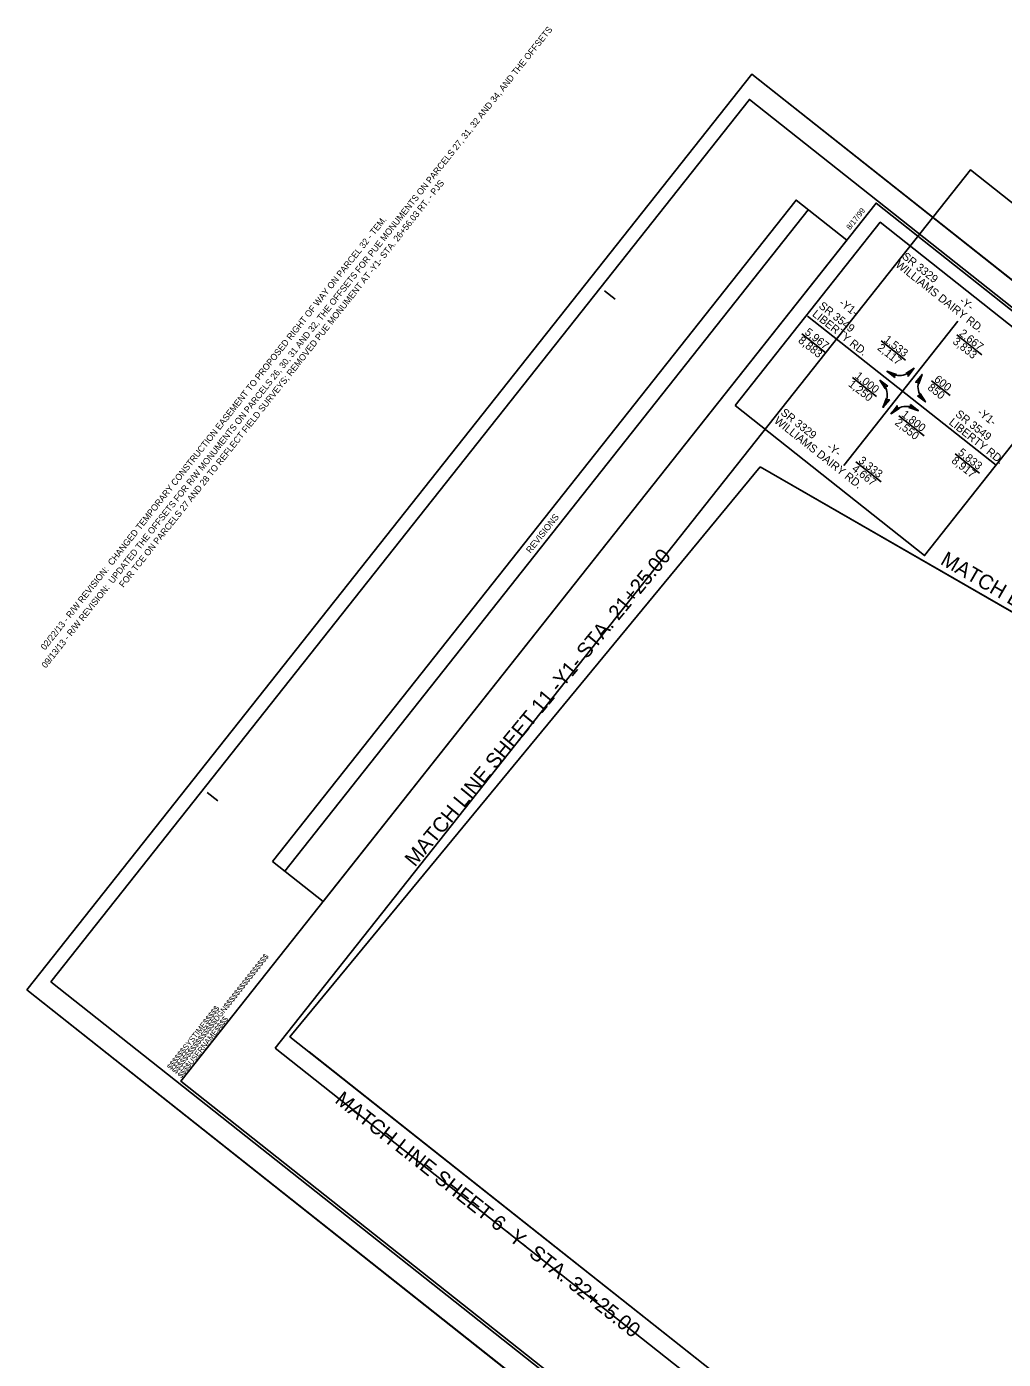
# Model space of a CAD drawing. Extents: x 1781865 to 1783979, y 813086 to 815120.
# Drawn here: x 1781865 to 1782780, y 813871 to 815120 of the extents above; entities that cross this region are included whole.
import ezdxf

# ---------------------------------------------------------------- set-up
doc = ezdxf.new("R2010")
doc.units = 0
for name, color, linetype in [('Matchline', 7, 'Continuous'), ('Matchline Text', 7, 'Continuous'), ('Old_Level_45', 7, 'Continuous'), ('Sheet Block Revision CELL', 7, 'Continuous'), ('Sheet Clip Boundary CELL', 7, 'Continuous'), ('Sheet Cutting Line CELL', 7, 'Continuous'), ('Sheet Layout Plan Border', 7, 'Continuous'), ('Sheet Plan CELL', 7, 'Continuous'), ('Sheet Plan Layout CELL', 7, 'Continuous'), ('Sheet Plot Border Inside CELL', 7, 'Continuous'), ('Sheet Plot Border Outside CELL', 7, 'Continuous')]:
    doc.layers.add(name, color=color, linetype=linetype)

msp = doc.modelspace()

# ---------------------------------------------------------------- linework, layer by layer
at = {"layer": 'Matchline'}
for p, q in [((1782111.4, 814173.2), (1782552.2, 814707.5)), ((1783101.5, 814390.8), (1782552.2, 814707.5)), ((1782468.8, 813890.2), (1782111.4, 814173.2)), ((1782468.8, 813890.2), (1782129.4, 814159)), ((1782528.7, 813842.8), (1782162.8, 814132.5))]:
    msp.add_line(p, q, dxfattribs=at)
at = {"layer": 'Old_Level_45'}
for p, q in [((1782773.3, 814709), (1782596.5, 814848.7)), ((1782630.5, 814708.6), (1782737.4, 814843.9)), ((1782591.3, 814832.2), (1782614.1, 814814.1)), ((1782736.4, 814831.2), (1782760, 814812.5)), ((1782665.7, 814825.4), (1782688.5, 814807.3)), ((1782638.6, 814791.2), (1782661.4, 814773.2)), ((1782712.8, 814788.1), (1782730.2, 814774.3)), ((1782682.2, 814755.2), (1782705.9, 814736.5)), ((1782735, 814719.5), (1782757.7, 814701.5)), ((1782641.9, 814712), (1782665.6, 814693.2))]:
    msp.add_line(p, q, dxfattribs=at)
for points in [[(1782528.7, 814764.8), (1782664.8, 814936.7), (1782842.3, 814796.1), (1782706.3, 814624.2)], [(1782678.3, 814791.1), (1782671, 814797), (1782679.9, 814793.9), (1782678, 814793)], [(1782688.7, 814794.8), (1782696.5, 814799.9), (1782690.8, 814792.4), (1782690.6, 814794.5)], [(1782700.8, 814785.1), (1782704, 814794), (1782698, 814786.7), (1782700.1, 814786.9)], [(1782671.8, 814782.9), (1782664.4, 814788.6), (1782669.5, 814780.7), (1782669.9, 814782.7)], [(1782670.6, 814771.9), (1782667.3, 814763.1), (1782673.4, 814770.3), (1782671.3, 814770.1)], [(1782682.7, 814762.3), (1782674.9, 814757.1), (1782680.5, 814764.7), (1782680.8, 814762.6)], [(1782693.2, 814765.9), (1782700.6, 814760), (1782691.7, 814763.1), (1782693.5, 814764)], [(1782699.7, 814774.1), (1782707.1, 814768.3), (1782702.1, 814776.3), (1782701.6, 814774.3)]]:
    msp.add_lwpolyline(points, close=True, dxfattribs=at)
for centre, start, end in [((1782682.3, 814811.2), 232.8741, 277.226), ((1782682.3, 814811.2), 277.226, 321.5778), ((1782718.3, 814782.7), 141.5801, 185.9319), ((1782653.1, 814774.3), 6.0359, 50.3878), ((1782718.3, 814782.7), 185.9319, 230.2838), ((1782653.1, 814774.3), 321.684, 6.0359), ((1782689.1, 814745.9), 97.3299, 141.6818), ((1782689.1, 814745.9), 52.9781, 97.3299)]:
    msp.add_arc(centre, 18.2, start, end, dxfattribs=at)
at = {"layer": 'Sheet Block Revision CELL'}
msp.add_line((1782106.6, 814328.5), (1782597.3, 814948.4), dxfattribs=at)
msp.add_lwpolyline([(1782095.2, 814337.6), (1782585.9, 814957.5), (1782633.4, 814919.9), (1782142.6, 814300)], close=True, dxfattribs=at)
at = {"layer": 'Sheet Clip Boundary CELL'}
msp.add_lwpolyline([(1782552.2, 814707.5), (1782111.4, 814173.2), (1782528.7, 813842.8), (1782497.5, 813772.1), (1782783.1, 813661.2), (1782870.1, 813592.2), (1782852, 813569.4), (1783166.6, 813320.4), (1783243.8, 813293.9), (1783730.1, 813908.2), (1783580.1, 814026.9), (1783674.7, 814147.7), (1783547.9, 814248.1), (1783381.9, 814035.5), (1783080.3, 814276), (1783101.5, 814390.8)], close=True, dxfattribs=at)
at = {"layer": 'Sheet Cutting Line CELL'}
for p, q in [((1782544.4, 815075.6), (1781864.7, 814217.1)), ((1783864.3, 814030.7), (1782544.4, 815075.6)), ((1781864.7, 814217.1), (1783184.6, 813172.1))]:
    msp.add_line(p, q, dxfattribs=at)
at = {"layer": 'Sheet Layout Plan Border'}
msp.add_lwpolyline([(1782097.5, 814162.5), (1783195.2, 813293.5), (1783715.7, 813950.9), (1783567.3, 814068.4), (1783698.6, 814234.2), (1782749.3, 814985.7)], close=True, dxfattribs=at)
at = {"layer": 'Sheet Plan CELL'}
for p, q in [((1782660.9, 814954.7), (1782660.9, 814954.7)), ((1782406.4, 814872.4), (1782416.2, 814864.6)), ((1782034, 814402), (1782043.8, 814394.2)), ((1782009.2, 814131.4), (1782009.2, 814131.4))]:
    msp.add_line(p, q, dxfattribs=at)
for points in [[(1783837, 814023.6), (1782660.9, 814954.7), (1782009.2, 814131.4), (1783185.2, 813200.3)], [(1782009.2, 814131.4), (1782660.9, 814954.7), (1783680.1, 814147.8), (1783587, 814030.1), (1783743.8, 813905.9), (1783185.2, 813200.3)]]:
    msp.add_lwpolyline(points, close=True, dxfattribs=at)
at = {"layer": 'Sheet Plan Layout CELL'}
msp.add_lwpolyline([(1782660.9, 814954.7), (1782009.2, 814131.4), (1783185.2, 813200.4), (1783705.7, 813857.8), (1783518.1, 814006.3), (1783649.4, 814172.1)], close=True, dxfattribs=at)
at = {"layer": 'Sheet Plot Border Inside CELL'}
msp.add_lwpolyline([(1781887.3, 814224.7), (1783193.5, 813190.6), (1783848.3, 814017.8), (1782542.1, 815051.9)], close=True, dxfattribs=at)
at = {"layer": 'Sheet Plot Border Outside CELL'}
msp.add_lwpolyline([(1781864.7, 814217.1), (1783184.6, 813172.1), (1783864.3, 814030.7), (1782544.4, 815075.6)], close=True, dxfattribs=at)

# ---------------------------------------------------------------- texts
at = {"layer": 'Matchline Text'}
for s, rotation, p in [('MATCH LINE SHEET 11 -Y1- STA. 21+25.00', 50.4514, (1782228.6, 814331.7)), ('MATCH LINE SHEET 7 -Y- STA. 25+00.00', 329.9225, (1782720.2, 814616.7)), ('MATCH LINE SHEET 6 -Y- STA. 32+25.00', 321.6215, (1782152.7, 814112.1))]:
    msp.add_text(s, height=14, rotation=rotation, dxfattribs=at).set_placement(p)
at = {"layer": 'Old_Level_45'}
for s, rotation, p in [('SR 3329', 321.6311, (1782684.6, 814903.4)), ('WILLIAMS DAIRY RD.', 321.6311, (1782678.5, 814895.7)), ('-Y-', 321.4626, (1782738.3, 814861.8)), ('LIBERTY RD.', 321.683, (1782600.4, 814849.4)), ('SR 3549', 321.683, (1782606.5, 814857.1)), ('-Y1-', 322.1568, (1782625.5, 814859.8)), ('8,883', 321.6312, (1782587.2, 814824.7)), ('5,967', 321.6312, (1782593.3, 814832.4)), ('1,533', 321.6312, (1782667.5, 814825.5)), ('3,833', 321.6312, (1782732, 814823.7)), ('2,667', 321.6312, (1782738.1, 814831.4)), ('2,117', 321.6312, (1782661.4, 814817.8)), ('1,000', 321.6312, (1782640.4, 814791.4)), ('600', 321.6312, (1782714.6, 814788.2)), ('1,250', 321.6312, (1782634.3, 814783.7)), ('850', 321.6312, (1782708.5, 814780.5)), ('WILLIAMS DAIRY RD.', 321.6311, (1782564.7, 814749.4)), ('SR 3329', 321.6311, (1782570.8, 814757.1)), ('2,550', 321.6312, (1782677.8, 814747.7)), ('1,800', 321.6312, (1782684, 814755.4)), ('LIBERTY RD.', 321.683, (1782728.5, 814747.9)), ('SR 3549', 321.683, (1782734.6, 814755.6)), ('-Y1-', 322.1568, (1782755, 814757.2)), ('-Y-', 321.4626, (1782614.1, 814724.9)), ('3,333', 321.6312, (1782643.7, 814712.1)), ('8,917', 321.6312, (1782730.9, 814712)), ('5,833', 321.6312, (1782737, 814719.7)), ('4,667', 321.6312, (1782637.6, 814704.4))]:
    msp.add_text(s, height=7.5, rotation=rotation, dxfattribs=at).set_placement(p)
at = {"layer": 'Sheet Block Revision CELL'}
for s, rotation, p in [('09/13/13 - R/W REVISION:  UPDATED THE OFFSETS FOR R/W MONUMENTS ON PARCELS 26, 30, 31 AND 32, THE OFFSETS FOR PUE MONUMENTS ON PARCELS 27, 31, 32 AND 34, AND THE OFFSETS', 51.5745, (1781882.7, 814518.2)), ('FOR TCE ON PARCELS 27 AND 28 TO REFLECT FIELD SURVEYS; REMOVED PUE MONUMENT AT -Y1- STA. 26+56.03 RT. - PJS', 51.5745, (1781955.4, 814593.8)), ('02/22/13 - R/W REVISION:  CHANGED TEMPORARY CONSTRUCTION EASEMENT TO PROPOSED RIGHT OF WAY ON PARCEL 32 - TEM. ', 51.5745, (1781881.9, 814535.1)), ('REVISIONS', 51.6309, (1782336.9, 814626))]:
    msp.add_text(s, height=6, rotation=rotation, dxfattribs=at).set_placement(p)
at = {"layer": 'Sheet Plan CELL'}
for s, p in [('8/17/99', (1782636.5, 814929.1)), ('$$$$$$$$$$$$$$$$DGN$$$$$$$$$$$$$$$$', (1782004.6, 814138)), ('$$$$$$SYSTIME$$$$$', (1781999.9, 814141.8)), ('$$$$USERNAME$$$$', (1782009.8, 814134))]:
    msp.add_text(s, height=5.25, rotation=51.6309, dxfattribs=at).set_placement(p)

doc.saveas('drawing.dxf')
